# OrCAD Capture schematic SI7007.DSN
size B; title: Si7022/7023 postage stamp; rev: 1.0
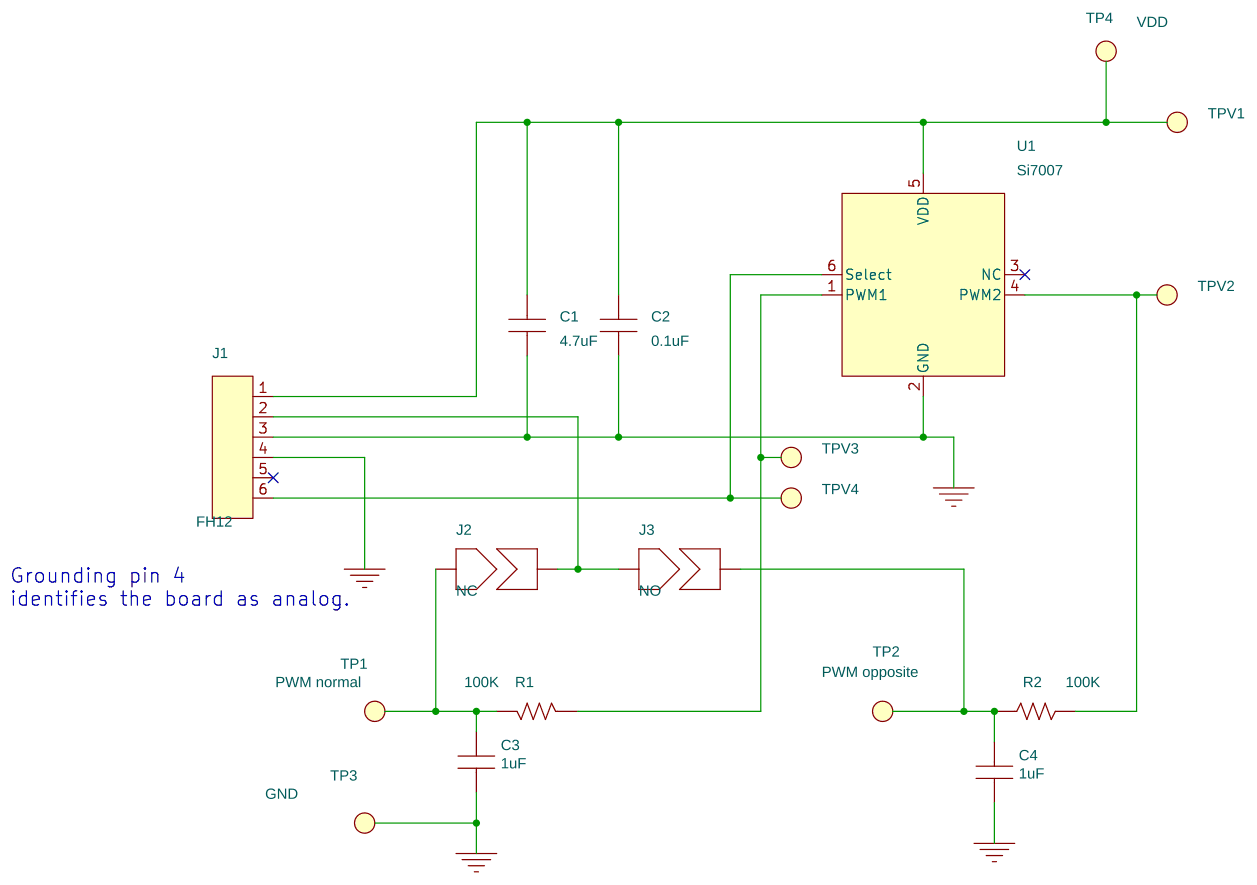
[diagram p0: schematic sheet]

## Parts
C1  4.7uF  [C0603]
C2  0.1uF  [C0402]
C3  1uF  [C0603]
C4  1uF  [C0603]
J1  FH12  [CONN6N-FPC/FFC-P0.5]
J2  NC  [SB0402-NC]
J3  NO  [SB0402-NO]
R1  100K  [R0603]
R2  100K  [R0603]
TP1  BLACK  [TESTPOINT]
TP2  BLACK  [TESTPOINT]
TP3  BLACK  [TESTPOINT]
TP4  RED  [TESTPOINT]
TPV1  TPV  [VIA-TP]
TPV2  TPV  [VIA-TP]
TPV3  TPV  [VIA-TP]
TPV4  TPV  [VIA-TP]
U1  Si7007  [DFN6M3X3P1.0E]

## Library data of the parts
C1 = CAP_NP: CAP, 4.7uF, 6.3V, ±10%, X5R, 0603; Manufacturer: Venkel; ManufacturerPN: C0603X5R6R3-475K; Part_Type: CAP/NP; SiLabsPN: C0603X5R6R3-475K; Tolerance: ±10%; Type: X5R; Voltage: 6.3V; Datasheet: PID_C.pdf
C2 = CAP_NP: CAP, 0.1uF, 10V, ±10%, X7R, 0402; Manufacturer: Venkel; ManufacturerPN: C0402X7R100-104K; Part_Type: CAP/NP; SiLabsPN: C0402X7R100-104K; Tolerance: ±10%; Type: X7R; Voltage: 10V; Datasheet: PID_C.pdf
C3 C4 = CAP_NP: CAP, 1uF, 10V, ±10%, X5R, 0603; Manufacturer: Venkel; ManufacturerPN: C0603X5R100-105K; SiLabsPN: C0603X5R100-105K; Tolerance: ±10%; Type: X5R; Voltage: 10V; Datasheet: PID_C.pdf
J1 = CON6: CONN, 6-PIN , FPC/FFC, BOTTOM CONTACT, 0.5MM PITCH, SMD; Manufacturer: HIROSE; ManufacturerPN: FH12-6S-0.5SH(55); Part_Type: CON/MODULAR; SiLabsPN: FH12-6S-0.5SH(55); Datasheet: e58605370.pdf
J2 = SolderBump: SOLDER BUMP JUMPER, NC, 0402; Manufacturer: N/A; ManufacturerPN: N/A; Type: PCB Feature
J3 = SolderBump: SOLDER BUMP JUMPER, NO, 0402; Manufacturer: N/A; ManufacturerPN: N/A; Type: PCB Feature
R1 R2 = RES: RES, 100K, 1/10W, ±5%, ThickFilm, 0603; Manufacturer: Venkel; ManufacturerPN: CR0603-10W-104J; Rating: 1/10W; SiLabsPN: CR0603-10W-104J; Tolerance: ±5%; Type: ThickFilm; Datasheet: PID_CR.pdf
TP1 = TEST_POINT: TESTPOINT, BLACK, PTH; Manufacturer: Kobiconn; ManufacturerPN: 151-203-RC; SiLabsPN: 151-203; Silk: PWM normal; Type: Loop; Datasheet: KC-300780.pdf
TP2 = TEST_POINT: TESTPOINT, BLACK, PTH; Manufacturer: Kobiconn; ManufacturerPN: 151-203-RC; SiLabsPN: 151-203; Silk: PWM opposite; Type: Loop; Datasheet: KC-300780.pdf
TP3 = TEST_POINT: TESTPOINT, BLACK, PTH; Manufacturer: Kobiconn; ManufacturerPN: 151-203-RC; SiLabsPN: 151-203; Silk: GND; Type: Loop; Datasheet: KC-300780.pdf
TP4 = TEST_POINT: TEST POINT, PC MINI .040"D, RED; Manufacturer: Keystone; ManufacturerPN: 5000; SiLabsPN: 5000; Silk: VDD; Type: LOOP; Datasheet: Keystone_thm_datasheet.pdf
TPV1-TPV4 = TPV: TESTPOINT Via; Manufacturer: N/A; ManufacturerPN: N/A; Type: PCB Feature
U1 = SI7022: IC, Humidity and Temperature Sensor PWM mode, ±5% RH, ±0.4°C, DFN6; Manufacturer: SiLabs; ManufacturerPN: Si7007-A10-IM1; SiLabsPN: TMP-4402; Type: Humidity and Temperature

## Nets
GND: C1.1 C2.1 C3.2 C4.2 J1.3 J1.4 TP3.1(Point) U1.2(GND)
N16761461: C1.2 C2.2 J1.1 TP4.1(Point) TPV1.1(Point) U1.5(VDD)
N16761469: R1.1 TPV3.1(Point) U1.1(PWM1)
N16762421: J1.6 TPV4.1(Point) U1.6(Select)
N16764482: R2.2 TPV2.1(Point) U1.4(PWM2)
N16769324: C3.1 J2.1(IO1) R1.2 TP1.1(Point)
N16769801: C4.1 J3.2(IO2) R2.1 TP2.1(Point)
N16770831: J1.2 J2.2(IO2) J3.1(IO1)

Not connected (* = marked no-connect by the designer): J1 5*; U1 3(NC)*

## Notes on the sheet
- Grounding pin 4
  identifies the board as analog.
